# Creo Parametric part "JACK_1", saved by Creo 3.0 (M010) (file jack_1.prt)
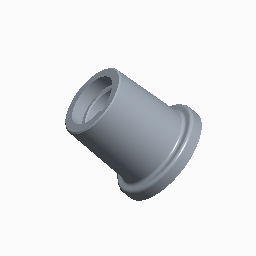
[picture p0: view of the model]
Units: millimeter Newton Second (mmNs); MM, TONNE, SECS

Created from: MMNS_PART_SOLID.PRT

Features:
  1. datum plane "RIGHT"
  2. datum plane "TOP"
  3. datum plane "FRONT"
  4. coordinate system
  5. protrusion
  6. round
  7. chamfer
  8. hole

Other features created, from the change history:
  planar section "A2-1"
